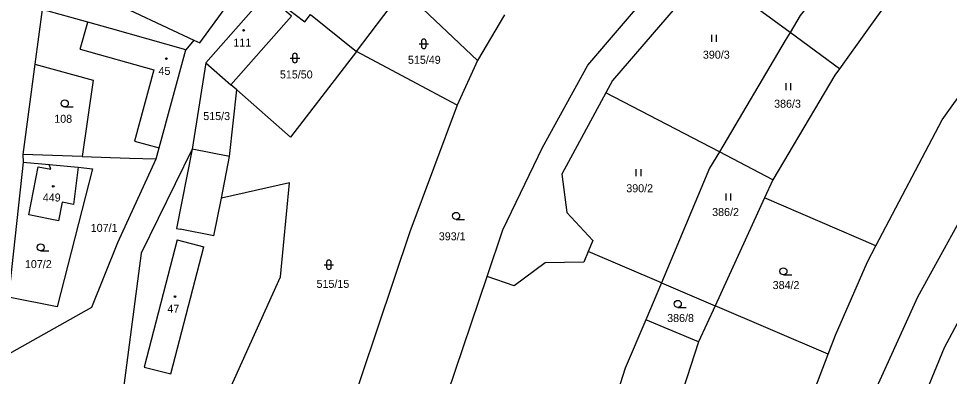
# Model space of a CAD drawing. Extents: x -725728 to -720881, y -1068679 to -1063504.
# Drawn here: x -722695.9 to -722498.2, y -1065579.4 to -1065503.4 of the extents above; entities that cross this region are included whole.
import ezdxf

# ---------------------------------------------------------------- set-up
doc = ezdxf.new("R2010")
doc.units = 0
for name, color, linetype in [('Hranice parcel', 7, 'Continuous'), ('Parcelní čísla', 7, 'Continuous'), ('Vnitřní kresba', 7, 'Continuous'), ('Značky budov', 7, 'Continuous'), ('Značky kultur', 7, 'Continuous')]:
    doc.layers.add(name, color=color, linetype=linetype)

# ---------------------------------------------------------------- blocks, each defined once
blk = doc.blocks.new('4.02_4')
at = {"layer": 'Značky budov'}
blk.add_circle((-0.001, 0), 0.0175, dxfattribs=at)
blk = doc.blocks.new('4.02_3')
at = {"layer": 'Značky budov'}
blk.add_circle((-0.001, 0), 0.0175, dxfattribs=at)
blk = doc.blocks.new('3.04_2')
at = {"layer": 'Značky kultur'}
blk.add_line((0.001, 0), (0.176, 0), dxfattribs=at)
blk.add_circle((0.001, 0.075), 0.075, dxfattribs=at)
blk = doc.blocks.new('3.16_2')
at = {"layer": 'Značky kultur'}
for p, q in [((-0.1, 0.1), (0.1, 0.1)), ((-0.05, 0.15), (-0.05, 0.05)), ((0.05, 0.05), (0.05, 0.15))]:
    blk.add_line(p, q, dxfattribs=at)
for centre, start, end in [((0, 0.15), 0, 180), ((0, 0.05), 180, 359.9879)]:
    blk.add_arc(centre, 0.05, start, end, dxfattribs=at)
blk = doc.blocks.new('3.06_1')
at = {"layer": 'Značky kultur'}
for p, q in [((-0.051, 0), (-0.051, 0.15)), ((0.049, 0), (0.049, 0.15))]:
    blk.add_line(p, q, dxfattribs=at)
blk = doc.blocks.new('3.06_2')
at = {"layer": 'Značky kultur'}
for p, q in [((-0.051, 0), (-0.051, 0.15)), ((0.049, 0), (0.049, 0.15))]:
    blk.add_line(p, q, dxfattribs=at)

msp = doc.modelspace()

# ---------------------------------------------------------------- linework, layer by layer
at = {"layer": 'Hranice parcel'}
for p, q in [((-722532.03, -1065506.39), (-722549.81, -1065493.34)), ((-722683.93, -1065496.12), (-722658.63, -1065508.01)), ((-722624.11, -1065510.44), (-722614.21, -1065497.39)), ((-722614.21, -1065497.39), (-722598.39, -1065512.36)), ((-722643.24, -1065498.25), (-722656.08, -1065512.82)), ((-722592.69, -1065502.66), (-722598.39, -1065512.36)), ((-722521.56, -1065514.09), (-722532.03, -1065506.39)), ((-722658.63, -1065508.01), (-722660.35, -1065510.05)), ((-722602.74, -1065521.83), (-722624.11, -1065510.44)), ((-722692.4, -1065513.08), (-722694.93, -1065532.29)), ((-722656.08, -1065512.82), (-722658.98, -1065531.16)), ((-722656.08, -1065512.82), (-722650.77, -1065517.5)), ((-722598.39, -1065512.36), (-722602.74, -1065521.83)), ((-722651.06, -1065532.72), (-722649.55, -1065518.57)), ((-722649.55, -1065518.57), (-722650.77, -1065517.5)), ((-722547.06, -1065531.76), (-722571.19, -1065519.22)), ((-722651.06, -1065532.72), (-722658.98, -1065531.16)), ((-722682.34, -1065532.71), (-722694.93, -1065532.29)), ((-722694.93, -1065532.29), (-722694.91, -1065533.91)), ((-722535.7, -1065537.67), (-722547.06, -1065531.76)), ((-722694.91, -1065533.91), (-722698, -1065562.6)), ((-722694.91, -1065533.91), (-722689.34, -1065534.43)), ((-722689.34, -1065534.43), (-722683.17, -1065535.01)), ((-722535.7, -1065537.67), (-722537.45, -1065541.49)), ((-722537.45, -1065541.49), (-722547.95, -1065564.4)), ((-722513.8, -1065551.72), (-722537.45, -1065541.49)), ((-722559.37, -1065559.52), (-722574.88, -1065552.87)), ((-722559.37, -1065559.52), (-722562.67, -1065567.37)), ((-722559.37, -1065559.52), (-722547.95, -1065564.4)), ((-722547.95, -1065564.4), (-722551.47, -1065572.09)), ((-722523.95, -1065574.66), (-722547.95, -1065564.4)), ((-722551.47, -1065572.09), (-722562.67, -1065567.37))]:
    msp.add_line(p, q, dxfattribs=at)
for points in [[(-722357.52, -1065354), (-722366.97, -1065367.42), (-722386.23, -1065395.85), (-722426.63, -1065447.77), (-722440.7, -1065466.38), (-722459.23, -1065491.7), (-722491.34, -1065537.79), (-722505.02, -1065562.62), (-722515.04, -1065584.73)], [(-722348.82, -1065361.62), (-722357.82, -1065375.76), (-722377.6, -1065403.63), (-722417.73, -1065451.78), (-722430.87, -1065469.56), (-722449.11, -1065495.01), (-722482.56, -1065541.98), (-722499.31, -1065573.36), (-722510.08, -1065599.54), (-722518.29, -1065629.02), (-722520.91, -1065639.92), (-722526.78, -1065669.58)], [(-722513.8, -1065551.72), (-722499.78, -1065524.95), (-722473.24, -1065487.78), (-722424.84, -1065424.64), (-722420.29, -1065418.95)], [(-722509.45, -1065477.18), (-722529.9, -1065502.75), (-722532.03, -1065506.39)], [(-722499.9, -1065484.77), (-722509.84, -1065497.77), (-722515.32, -1065505.39), (-722521.56, -1065514.09)], [(-722596.39, -1065558.21), (-722593.04, -1065548.26), (-722584.61, -1065530.77), (-722574.99, -1065513.33), (-722554.78, -1065489.69)], [(-722549.81, -1065493.34), (-722569.77, -1065516.58), (-722571.19, -1065519.22)], [(-722658.63, -1065508.01), (-722657.38, -1065508.6), (-722646.82, -1065494.06)], [(-722641.91, -1065496.7), (-722638.13, -1065499.62), (-722639.18, -1065500.98), (-722635.1, -1065504.14), (-722633.88, -1065502.58), (-722624.11, -1065510.44)], [(-722650.77, -1065517.5), (-722637.94, -1065502.93), (-722643.24, -1065498.25)], [(-722660.35, -1065510.05), (-722676.37, -1065505.55), (-722681.15, -1065504.21), (-722690.86, -1065501.48), (-722692.4, -1065513.08)], [(-722532.03, -1065506.39), (-722533.05, -1065508.11), (-722547.06, -1065531.76)], [(-722666.65, -1065533.23), (-722666.01, -1065530.86), (-722660.35, -1065510.05)], [(-722624.11, -1065510.44), (-722638.14, -1065528.61), (-722649.55, -1065518.57)], [(-722692.4, -1065513.08), (-722680.01, -1065516.48), (-722682.34, -1065532.71)], [(-722521.56, -1065514.09), (-722522.54, -1065515.45), (-722535.7, -1065537.67)], [(-722571.19, -1065519.22), (-722580.48, -1065536.47), (-722579.45, -1065544.58), (-722573.89, -1065550.58), (-722574.88, -1065552.87)], [(-722602.74, -1065521.83), (-722612.75, -1065548.74), (-722629.96, -1065599.94), (-722631.86, -1065609.47)], [(-722658.98, -1065531.16), (-722669.81, -1065553.25), (-722673.54, -1065581.37)], [(-722700.77, -1065576.21), (-722680.32, -1065564.72), (-722674.8, -1065550.97), (-722666.65, -1065533.23)], [(-722682.34, -1065532.71), (-722672.3, -1065533.04), (-722666.65, -1065533.23)], [(-722651.62, -1065583.51), (-722640.22, -1065558.3), (-722638.35, -1065538.33), (-722652.8, -1065541.59), (-722651.06, -1065532.72)], [(-722547.06, -1065531.76), (-722549.13, -1065535.22), (-722559.37, -1065559.52)], [(-722683.17, -1065535.01), (-722680.13, -1065535.3), (-722687.67, -1065564.66), (-722698, -1065562.6)], [(-722683.17, -1065535.01), (-722684.21, -1065542.91), (-722686.57, -1065542.44), (-722687.36, -1065546.39), (-722693.71, -1065545.12), (-722691.67, -1065534.88), (-722689.01, -1065535.41), (-722689.34, -1065534.43)], [(-722574.88, -1065552.87), (-722575.86, -1065555.17), (-722584.03, -1065555.29), (-722590.6, -1065560.15), (-722596.39, -1065558.21)], [(-722523.95, -1065574.66), (-722522.43, -1065570.64), (-722515.57, -1065555.09), (-722513.8, -1065551.72)], [(-722610.41, -1065613.59), (-722604.78, -1065583.14), (-722596.39, -1065558.21)], [(-722562.67, -1065567.37), (-722567.03, -1065577.69), (-722579.03, -1065615.22)], [(-722551.47, -1065572.09), (-722560.65, -1065600.25), (-722567.54, -1065628.62)], [(-722542.38, -1065632.14), (-722537.33, -1065610.22), (-722530.72, -1065592.53), (-722523.95, -1065574.66)]]:
    msp.add_lwpolyline(points, dxfattribs=at)
at = {"layer": 'Vnitřní kresba'}
for p, q in [((-722682.76, -1065509.95), (-722681.15, -1065504.21)), ((-722682.76, -1065509.95), (-722667.13, -1065514.34)), ((-722667.13, -1065514.34), (-722671.24, -1065529.44)), ((-722671.24, -1065529.44), (-722666.01, -1065530.86)), ((-722658.98, -1065531.16), (-722662.3, -1065547.99)), ((-722654.37, -1065549.55), (-722652.8, -1065541.59)), ((-722662.3, -1065547.99), (-722661.57, -1065548.13)), ((-722654.37, -1065549.55), (-722661.57, -1065548.13)), ((-722662.15, -1065550.39), (-722669.17, -1065577.44)), ((-722662.15, -1065550.39), (-722656.55, -1065551.89)), ((-722663.56, -1065578.9), (-722656.55, -1065551.89)), ((-722669.17, -1065577.44), (-722663.56, -1065578.9))]:
    msp.add_line(p, q, dxfattribs=at)

# ---------------------------------------------------------------- block references
at = {"layer": 'Značky budov', "xscale": 10, "yscale": 10}
for name, p in [('4.02_4', (-722648.07, -1065505.92)), ('4.02_3', (-722664.46, -1065511.94)), ('4.02_3', (-722688.5, -1065539.04)), ('4.02_3', (-722662.65, -1065562.46))]:
    msp.add_blockref(name, p, dxfattribs=at)
at = {"layer": 'Značky kultur', "xscale": 10, "yscale": 10}
for name, p in [('3.06_1', (-722548.12, -1065508.37)), ('3.16_2', (-722609.81, -1065509.79)), ('3.16_2', (-722637.17, -1065512.8)), ('3.06_2', (-722532.36, -1065518.65)), ('3.04_2', (-722686.06, -1065522.2)), ('3.06_2', (-722564.18, -1065536.88)), ('3.06_1', (-722545.09, -1065542.09)), ('3.04_2', (-722602.96, -1065546.08)), ('3.04_2', (-722691.19, -1065552.76)), ('3.16_2', (-722629.96, -1065556.71)), ('3.04_2', (-722533.46, -1065557.85)), ('3.04_2', (-722555.9, -1065564.77))]:
    msp.add_blockref(name, p, dxfattribs=at)

# ---------------------------------------------------------------- texts
at = {"layer": 'Parcelní čísla'}
for s, p in [('111', (-722650.25, -1065509.38)), ('515/49', (-722613.18, -1065513.03)), ('390/3', (-722550.55, -1065511.94)), ('45', (-722666.15, -1065515.39)), ('515/50', (-722640.37, -1065516.14)), ('386/3', (-722535.43, -1065522.36)), ('515/3', (-722656.64, -1065524.98)), ('108', (-722688.28, -1065525.56)), ('390/2', (-722566.82, -1065540.31)), ('449', (-722690.71, -1065542.27)), ('386/2', (-722548.59, -1065545.36)), ('107/1', (-722680.54, -1065548.72)), ('393/1', (-722606.63, -1065550.51)), ('107/2', (-722694.51, -1065556.42)), ('515/15', (-722632.59, -1065560.61)), ('384/2', (-722535.74, -1065560.87)), ('47', (-722664.25, -1065565.89)), ('386/8', (-722558.14, -1065567.87))]:
    msp.add_text(s, height=1.7, dxfattribs=at).set_placement(p)

doc.saveas('drawing.dxf')
